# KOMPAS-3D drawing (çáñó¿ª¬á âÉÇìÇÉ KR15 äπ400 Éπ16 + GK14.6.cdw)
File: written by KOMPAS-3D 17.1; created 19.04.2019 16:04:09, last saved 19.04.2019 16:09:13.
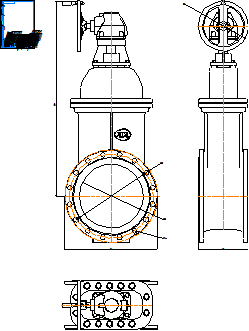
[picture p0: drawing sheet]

Sheet 1: A4, portrait

Title block, sheet 1: name: Задвижка ГРАНАР KR15 Ду400 Ру16 + GK14.6; material: Внимание! Данный продукт является объектом авторского права ООО «Торговый Дом АДЛ». / Запрещается изменение, копирование, распространение / (в том числе путем копирования на другие сайты и ресурсы в Интернете) / или любое иное использование информации и объектов без предварительного / согласия правообладателя (ООО «Торговый Дом АДЛ»).; mass: 541,89; sheets: 1; organisation: ООО "Торговый дом АДЛ"; sheet format: A4; stored path: \\adlc.lan\data\АДЛ_ПКД\3D-модели\ADL production\Клиновые задвижки серии KR ГРАНАР\Клиновые задвижки KR15\С редуктором\KOMPAS 2D\Задвижка ГРАНАР KR15 Ду400 Ру16 + GK14.6.cdw

Views: Вид 1, Проекционный вид 2, Проекционный вид 3
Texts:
  user
Dimensions and other numbers on the sheet: 400; 31; 16 Отв.; 310; 315; 1217,5; 580; 525; 1:1; 1; 541,89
